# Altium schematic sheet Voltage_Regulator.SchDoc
size A; SheetNumber: 4; SheetTotal: 5
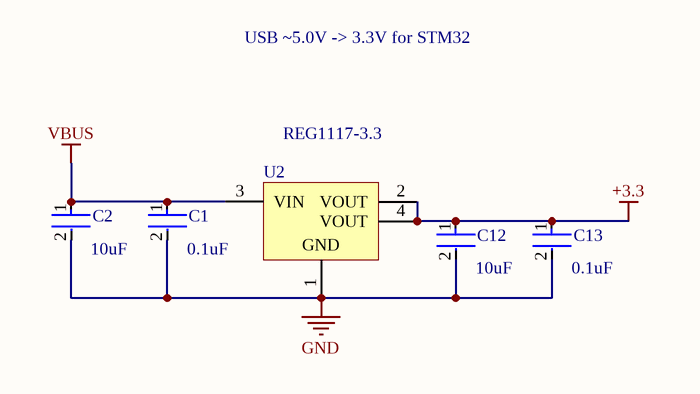
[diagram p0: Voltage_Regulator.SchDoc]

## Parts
C1  0.1uF  [CAPC0603(1608)100_L]
C2  10uF  [CAPC0603(1608)100_L]
C12  10uF  [CAPC0603(1608)100_L]
C13  0.1uF  [CAPC0603(1608)100_L]
U2  REG1117-3.3  [DCY0004A_M]

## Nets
+3.3: C12.1 C13.1 U2.2(VOUT) U2.4(VOUT)
GND: C1.2 C2.2 C12.2 C13.2 U2.1(GND)
VBUS: C1.1 C2.1 U2.3(VIN)

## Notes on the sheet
- USB ~5.0V -> 3.3V for STM32

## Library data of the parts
C1 C2 C12 C13 = CMP-001-00083-4: GENERIC CAPACITOR 0805 or 0603(1608)
U2 = CMP-019-00049-4: LDO Regulator Pos 3.3V 0.8A 4-Pin(3+Tab) SOT-223 Rail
